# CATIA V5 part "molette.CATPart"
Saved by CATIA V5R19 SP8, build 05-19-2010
Part number: molette
Revision: ANY
Definition: UNKNOWN
Nomenclature: 11
Source: Unknown
Bounding box of the stored display mesh (mm): x -27.278 to -14.278, y 0 to 11.489, z -11.472 to 11.472
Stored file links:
  D:\Documents\1_Travail\2- 2I2D\1 - Cours et TD\2- TD\3-TD Assemblage\Pompe AirMan\molette.CATPart
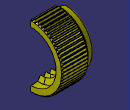
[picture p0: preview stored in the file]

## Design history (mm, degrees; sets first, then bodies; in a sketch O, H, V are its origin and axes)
Body1 "Enlèv. mat.-Extru.2" (main body)
  Solid1: solid without history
